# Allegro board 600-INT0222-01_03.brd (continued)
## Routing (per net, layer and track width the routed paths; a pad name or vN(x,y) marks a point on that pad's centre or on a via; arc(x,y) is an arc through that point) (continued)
P10_6_VBEMF_V/IV(2)_L: length 9
  BOTTOM w0.203: J13.3 51.28,3.95 51.58,4.25 51.58,8.67 J15.1
P10_6_VBEMF_V/IV(2)_R: length 13.5
  TOP w0.203: J15.3 56.94,8.95 52.82,8.95 51.6,7.73 51.6,4.43 51.28,4.11 J13.4
P10_7_VBEMF_V/IV(3)/PFC_I_PHASE_IN_B: length 95.9
  TOP w0.203: v1(18.94,49.34) 19.28,49 19.28,45 18.25,43.97 16.66,43.97 16.13,43.43 16.13,43.05 15.23,42.15 13.69,42.15 12.79,43.05 11.88,43.05 10.98,42.15 8.73,42.15 J1.B29 ; J19.2 56.99,65.82 56.01,66.8 51.99,66.8 51.52,67.27 44.78,67.27 43.71,68.34 42.99,68.34 J5.16 41.67,68.2 42.14,67.73 43.25,67.73 44.48,66.5 49.96,66.5 51.09,65.37 51.09,63.59 48.51,61.02 48.51,56.65 48.07,56.21 47.42,56.21 v1(47.01,55.79) J12.C7
  L03_SIG1 w0.203: v1(18.94,49.34) 19.28,49.68 19.28,50.85 21.19,52.76 46.03,52.76 48.01,54.74 48.01,55.95 47.73,56.23 47.44,56.23 v1(47.01,55.79)
P10_7_VBEMF_V/IV(3)/PFC_I_PHASE_IN_B_L: length 21.5
  BOTTOM w0.203: J19.1 55.72,65.8 63.54,65.8 64.18,66.43 68.29,66.43 69.87,68.01 69.87,70.59 70.14,70.86 J2.3
P10_7_VBEMF_V/IV(3)/PFC_I_PHASE_IN_B_N: length 79.8
  TOP w0.203: J5.17 42.85,70.83 41.18,70.83 40.49,70.14 40.49,68.81 41.97,67.33 43.08,67.33 44.31,66.1 49.79,66.1 50.68,65.2 50.68,63.76 48.11,61.19 48.11,56.82 47.9,56.62 47.46,56.62 v1(47.01,57.07) J12.B7 ; v1(20.03,49.34) 19.68,49 19.68,44.83 18.41,43.56 16.83,43.56 16.59,43.32 R20.1 16.07,42.42 15.4,41.74 13.52,41.74 13.12,42.15 12.54,42.15 J1.A29
  L03_SIG1 w0.203: v1(20.03,49.34) 19.68,49.68 19.68,50.68 21.36,52.36 46.2,52.36 48.41,54.57 48.41,56.12 47.9,56.64 47.44,56.64 v1(47.01,57.07)
P10_7_VBEMF_V/IV(3)/PFC_I_PHASE_IN_B_R: length 23.8
  TOP w0.203: v1(73.95,65.52) 73.95,65.75 70.14,69.56 J2.4
  L03_SIG1 w0.203: J19.3 60.91,65.91 73.56,65.91 v1(73.95,65.52)
P11_0_VBEMF_U/IU(1): length 121.8
  TOP w0.203: v1(90.21,33.39) 87.88,35.71 87.88,40.51 89.76,42.39 93.86,42.39 96.59,45.12 98.39,45.12 J4.A5 ; v1(50.9,28.02) 50.56,28.36 49.75,28.36 49.55,28.15 J10.C8
  L03_SIG1 w0.203: v1(90.21,33.39) 87.43,30.61 52.83,30.61 51.69,29.46 51.69,28.24 51.46,28.02 v1(50.9,28.02) 50.56,28.36 50.27,28.36 49.94,28.02 49.94,26.44 47.6,24.1 22.77,24.1 21.01,22.34 21.01,17.2 19.15,15.34 17.75,15.34 17.14,14.73 17.14,12.36 16.35,11.56 13.74,11.56 12.57,12.74 J1.B6
P11_0_VBEMF_U/IU(1)_N: length 55.7
  TOP w0.203: R23.1 14.28,12.7 J1.A6 ; J10.B8 49.55,28.97 49.75,28.76 50.56,28.76 v1(50.9,29.11)
  L03_SIG1 w0.203: J1.A6 14.22,12.72 14.97,11.97 16.18,11.97 16.74,12.53 16.74,14.9 17.59,15.75 18.98,15.75 20.6,17.36 20.6,22.5 22.61,24.51 47.43,24.51 49.53,26.61 49.53,28.19 50.11,28.76 50.56,28.76 v1(50.9,29.11)
P11_1_VBEMF_V/IV(1): length 119.8
  TOP w0.203: v1(47.01,28.02) J10.C7 ; J4.A6 98.39,42.58 96.59,42.58 95.41,41.4 89.79,41.4 88.62,40.23 88.62,36.6 v1(90.21,35.01)
  L03_SIG1 w0.203: v1(90.21,35.01) 86.69,31.5 47.37,31.5 46.41,30.53 46.41,28.62 v1(47.01,28.02) 47.38,28.39 47.67,28.39 48.15,27.91 48.15,26.94 46.74,25.53 21.84,25.53 18.2,21.88 18.2,18.65 15.47,15.92 15.47,14.65 15.03,14.21 13.8,14.21 12.94,15.07 11.73,15.07 10.67,14.01 J1.B7
P11_1_VBEMF_V/IV(1)_N: length 54
  TOP w0.203: v1(47.01,29.18) J10.B7 ; R16.1 12.42,14.1 J1.A7
  L03_SIG1 w0.203: J1.A7 13.43,14.01 13.63,13.8 15.2,13.8 15.88,14.48 15.88,15.75 18.61,18.48 18.61,21.71 22.01,25.12 46.9,25.12 48.56,26.77 48.56,28.08 47.84,28.8 47.38,28.8 v1(47.01,29.18)
P11_2_VBEMF_W/IW(1): length 112.3
  TOP w0.203: v1(90.21,36.92) 89.28,37.85 89.28,39.62 90.18,40.52 95.37,40.52 95.85,40.04 98.39,40.04 J4.A7 ; v1(44.47,28.02) J10.C6
  L03_SIG1 w0.203: v1(90.21,36.92) 90.13,36.92 85.34,32.13 45.47,32.13 43.87,30.53 43.87,28.62 v1(44.47,28.02) 44.84,28.39 45.13,28.39 45.39,28.14 45.39,27.42 44.41,26.44 21.11,26.44 17.27,22.61 17.27,19.34 14.68,16.75 14.05,16.75 12.78,15.48 10.63,15.48 J1.B8
P11_2_VBEMF_W/IW(1)_N: length 46.5
  TOP w0.203: v1(44.47,29.18) J10.B6 ; J1.A8 15.6,16.64 R17.1
  L03_SIG1 w0.203: J1.A8 14.24,15.73 17.68,19.17 17.68,22.44 21.28,26.04 44.58,26.04 45.8,27.25 45.8,28.3 45.3,28.8 44.84,28.8 v1(44.47,29.18)
P12_0_PFC_V_PHASE_IN_B: length 193.5
  TOP w0.203: v1(86.12,11.87) 87.11,12.87 87.11,49.19 v1(86.11,50.2) 86.58,50.67 96.12,50.67 96.59,50.2 98.39,50.2 J4.A4 ; J12.C17 v1(72.41,55.87) 71.17,57.1 71.17,61.45 72.39,62.67 72.39,65.58 70.71,67.27 63.79,67.27 62.86,68.21 62.86,72.4 61.74,73.52 59.47,73.52 J8.7
  L03_SIG1 w0.203: J7.7 64.39,3.98 64.39,6.55 65.93,8.09 73.75,8.09 78.36,12.7 85.29,12.7 v1(86.12,11.87) ; v1(86.11,50.2) 82.6,53.71 74.57,53.71 v1(72.41,55.87) 72.41,55.98 71.59,56.8 71.59,57.08 68.56,60.12 21.73,60.12 18.31,63.54 J1.A46
P12_5_PFC_OVERCURRENT_PROT: length 73.6
  TOP w0.305: J12.C19 v1(77.49,55.87)
  L03_SIG1 w0.203: J1.A47 12.33,65.76 13.91,67.34 20.58,67.34 25.35,62.56 70.8,62.56 v1(77.49,55.87)
P12_6_PFC_NTC: length 76.4
  TOP w0.203: J12.B19 v1(77.49,57.13)
  L03_SIG1 w0.203: J1.B48 10.43,67.03 13.14,69.74 15.86,69.74 16.38,69.22 20.14,69.22 26.19,63.17 71.45,63.17 v1(77.49,57.13)
P13_0_U3_H/PFC_PWM_A_1: length 113.7
  TOP w0.152: J12.C1 v1(31.77,55.79)
  LO4_SIG2 w0.152: J5.1 22.55,70.85 22.55,66.08 30.73,57.89 30.73,56.82 v1(31.77,55.79) 31.77,49.9 v1(29.73,47.87)
  BOTTOM w0.152: v1(29.73,47.87) 27.84,45.97 16.8,45.97 15.52,47.25 13.73,47.25 12.69,48.3 J1.B34 ; J2.17 75.74,70.98 76.33,70.39 76.52,70.39 77.38,69.53 77.38,63.92 74.62,61.15 33.84,61.15 30.86,58.17 30.86,56.7 v1(31.77,55.79)
P13_1_U3_L/PFC_PWM_A_2: length 108.1
  TOP w0.152: J12.B1 v1(31.77,57.07)
  LO4_SIG2 w0.152: J5.3 25.12,70.89 25.12,64.82 31.77,58.18 v1(31.77,57.07) 32.64,56.2 32.64,49.23 30.4,46.99 28.96,46.99 28.11,47.84 v1(28.11,47.87)
  BOTTOM w0.152: v1(28.11,47.87) 27.23,46.99 19.3,46.99 18,48.3 J1.A34 ; v1(31.77,57.07) 32.1,57.4 32.21,57.4 35.45,60.64 75.02,60.64 78.27,63.89 78.27,69.29 76.54,71.02 J2.19
P13_2_V3_H/PFC_PWM_B_1: length 110.6
  TOP w0.152: J12.B2 v1(34.31,57.07)
  LO4_SIG2 w0.152: v1(34.31,57.07) 27.66,63.72 27.66,70.89 J5.5
  BOTTOM w0.152: J2.31 81.34,65.08 75.83,59.57 36.81,59.57 v1(34.31,57.07) 34.84,56.54 34.84,54.78 32.38,52.32 13.59,52.32 12.77,53.15 11.9,53.15 10.85,52.1 10.11,52.1 8.53,50.51 J1.B35
P13_3_V3_L/PFC_PWM_B_2: length 120.4
  TOP w0.152: J12.C2 v1(34.31,55.79)
  LO4_SIG2 w0.152: J5.7 30.25,70.94 30.25,68.33 30.81,67.77 30.81,62.2 35.18,57.84 35.18,56.67 v1(34.31,55.79)
  BOTTOM w0.152: J2.29 80.54,65.3 75.38,60.13 35.75,60.13 33.66,58.04 33.66,56.44 v1(34.31,55.79) 34.31,55.69 31.32,52.7 16.64,52.7 14.73,54.61 14,54.61 13,53.61 11.9,53.61 11.09,54.42 10,54.42 8.79,53.21 8.16,53.21 7.48,52.54 7.48,49.14 8.09,48.53 9.03,48.53 10.07,49.57 J1.A35
P13_4_W3_H/PFC_PWM_C_1: length 107.3
  TOP w0.152: v1(35.9,56.06) 35.9,55.71 36.85,54.77 J12.C3
  LO4_SIG2 w0.152: J5.9 32.91,71.06 32.91,69.19 34.8,67.3 34.8,60.5 35.9,59.4 v1(35.9,56.06)
  BOTTOM w0.152: J1.B36 12.77,50.84 13.87,51.94 33.1,51.94 35.9,54.75 v1(35.9,56.06) 35.9,57.37 37.65,59.12 76.39,59.12 82.14,64.86 J2.33
P13_5_W3_L/PFC_PWM_C_2: length 102.5
  TOP w0.152: J12.B3 v1(36.85,57.07)
  LO4_SIG2 w0.152: v1(36.85,57.07) 37.19,57.41 37.19,64.75 36.59,65.34 36.59,68.05 37.73,69.19 37.73,71.06 J5.11
  BOTTOM w0.152: J1.A36 14.46,51.05 33.4,51.05 36.85,54.5 v1(36.85,57.07) 38.38,58.61 77.03,58.61 82.94,64.52 J2.35
P14_0_V4_H: length 128.4
  TOP w0.152: J9.C13 v1(62.25,45.63)
  LO4_SIG2 w0.152: J1.B39 10.76,54.65 11.8,55.69 12.92,55.69 13.73,54.88 17.13,54.88 20.95,51.05 20.95,47.57 25.74,42.79 59.4,42.79 v1(62.25,45.63)
  BOTTOM w0.152: J6.5 93.54,3.92 93.54,10.55 84.28,19.81 82.69,19.81 79.07,23.44 79.07,39.75 76.28,42.55 65.33,42.55 v1(62.25,45.63)
P16_3_ADC_BOARDIDENT/EXTRA_ADC4: length 59.4
  TOP w0.203: J12.C15 67.33,55.58 65.95,56.96 v1(64.79,56.96) J12.B14
  L03_SIG1 w0.203: J1.A44 15.21,61 17.33,58.88 19.42,58.88 19.8,58.49 63.25,58.49 v1(64.79,56.96)
P17_0_PFC_V_PHASE_IN_C: length 71.5
  TOP w0.203: J12.C18 v1(74.95,55.87)
  L03_SIG1 w0.203: J1.B46 12.65,63.54 13.81,64.69 15.16,64.69 16.04,65.57 19.42,65.57 23.65,61.34 69.48,61.34 v1(74.95,55.87)
P17_3_VBEMF_W/IW(4): length 122.3
  TOP w0.203: v1(24.87,49.59) 24.87,50.61 15.75,59.73 J1.A43 ; v1(84,41.9) 82.8,40.7 82.8,9.6 80.3,7.1 78.93,7.1 J6.18 ; J9.C7 v1(47.01,45.71)
  L03_SIG1 w0.203: v1(84,41.9) 81.57,41.9 80.44,43.03 49.69,43.03 v1(47.01,45.71) 42.77,49.95 25.22,49.95 v1(24.87,49.59)
P17_4_VBEMF_W/IW(2): length 119.9
  TOP w0.203: v1(44.47,17.77) J11.C6 44.47,11.92 J16.2 ; v1(24.55,20.84) 16.14,29.25 13.92,29.25 12.73,30.44 12,30.44 10.81,29.25 J1.B19
  L03_SIG1 w0.203: v1(24.55,20.84) 25.35,21.64 43.19,21.64 45.28,19.55 45.28,18.58 v1(44.47,17.77) 46.12,16.12 51.48,16.12 52.81,17.45 52.81,19.48 56.06,22.73 81.04,22.73 81.05,22.74 83.07,22.74 93.89,33.57 93.89,38.21 96.99,41.31 J4.B7
P17_4_VBEMF_W/IW(2)_L: length 13.4
  L03_SIG1 w0.203: v1(48.4,7.4) 47.04,8.76 45.09,8.76 J16.1
  BOTTOM w0.203: J13.5 50.48,4.02 50.97,4.51 50.97,5.96 50.13,6.79 49.01,6.79 v1(48.4,7.4)
P17_4_VBEMF_W/IW(2)_R: length 9.5
  TOP w0.203: J13.6 50.48,4.19 50.97,4.69 50.97,6.42 v1(49.78,7.61)
  L03_SIG1 w0.203: J16.3 49.78,9.14 v1(49.78,7.61)
P17_5_VBEMF_W/IW(3)/PFC_I_PHASE_IN_C: length 105.4
  TOP w0.203: 62,62.89 60.71,61.59 51.44,61.59 51.05,61.21 51.05,56.68 50.61,56.24 49.99,56.24 v1(49.55,55.79) J12.C8 ; 62,62.89 62,65.12 59.27,67.84 52.49,67.84 52.11,68.22 49.36,68.22 48.49,69.1 48.49,72.31 47.31,73.49 46.19,73.49 45.47,72.76 45.47,70.91 J5.18 ; 62,62.89 62.3,62.59 65.64,62.59 J20.2
  L03_SIG1 w0.203: J1.B30 12.73,43.22 14.12,44.6 14.84,44.6 14.89,44.55 18.42,44.55 20.92,47.05 20.92,50.58 22.02,51.67 49,51.67 50.93,53.59 50.93,55.63 50.32,56.23 49.98,56.23 v1(49.55,55.79)
P17_5_VBEMF_W/IW(3)/PFC_I_PHASE_IN_C_L: length 11.8
  BOTTOM w0.203: J2.5 70.94,70.8 70.48,70.34 70.48,67.76 68.54,65.82 66.33,65.82 J20.1
P17_5_VBEMF_W/IW(3)/PFC_I_PHASE_IN_C_N: length 91.9
  TOP w0.203: J12.B8 v1(49.55,57.07) 49.98,56.64 50.44,56.64 50.65,56.85 50.65,61.38 51.27,62 60.54,62 61.59,63.06 61.59,64.95 59.11,67.44 52.32,67.44 51.94,67.82 49.19,67.82 48.08,68.93 48.08,70.87 J5.19 ; R21.1 16.23,45.21 J1.A30
  L03_SIG1 w0.203: v1(49.55,57.07) 49.98,56.64 50.49,56.64 51.33,55.79 51.33,53.43 49.17,51.27 22.19,51.27 21.33,50.41 21.33,46.88 18.59,44.15 15.06,44.15 14.24,43.32 J1.A30
P17_5_VBEMF_W/IW(3)/PFC_I_PHASE_IN_C_R: length 17.7
  TOP w0.203: v1(74.73,67.51) 74.67,67.51 73.35,68.83 71.91,68.83 70.94,69.8 J2.6
  L03_SIG1 w0.203: v1(74.73,67.51) 74.73,67.41 75.61,66.53 75.61,64.18 74.55,63.12 72.92,63.12 71.51,64.53 J20.3
P17_6_IAVG_IDCLINK(3): length 89
  TOP w0.203: J5.14 39.13,68.12 42.04,65.21 42.04,63.78 42.89,62.93 45.1,62.93 J21.2 46.6,61.84 45.85,61.09 45.85,56.58 45.39,56.12 44.79,56.12 v1(44.47,55.79) J12.C6
  L03_SIG1 w0.203: J8.6 54.22,68.26 40.53,68.26 J5.14 ; J1.B31 8.52,45.46 10.09,47.03 10.76,47.03 11.87,48.13 12.8,48.13 13.71,47.23 15.86,47.23 17.02,48.39 17.02,51.25 19.64,53.87 44.73,53.87 45.59,54.74 45.59,55.83 45.18,56.24 44.91,56.24 v1(44.47,55.79)
P17_6_IAVG_IDCLINK(3)_L: length 39.6
  BOTTOM w0.203: J21.1 45.87,62.61 71.48,62.61 73.02,64.15 73.02,66.42 73.8,67.21 73.8,68.82 72.66,69.97 72.66,70.85 72.54,70.97 J2.9
P17_6_IAVG_IDCLINK(3)_N: length 50.8
  TOP w0.203: R24.1 15.31,45.32 15.31,45.32 14.68,44.69 14.68,44.69 14.47,44.49 J1.A31 ; J12.B6 v1(44.47,57.07)
  L03_SIG1 w0.203: J1.A31 12.33,45.48 13.68,46.82 16.03,46.82 17.42,48.22 17.42,51.08 19.81,53.47 44.9,53.47 46,54.57 46,55.99 45.35,56.64 44.9,56.64 v1(44.47,57.07)
P17_7_IDCLINK(4): length 156.8
  TOP w0.203: v1(84,43.8) 82.08,41.88 82.08,10.07 80.38,8.37 68.77,8.37 J7.6 ; v1(22.14,50.07) 22.14,50.46 17.61,54.99 14.99,54.99 14.6,54.61 13.97,54.61 12.62,55.96 11.99,55.96 10.71,57.24 10.05,57.24 8.52,58.76 J1.B43 ; J9.B7 v1(47.01,46.97)
  L03_SIG1 w0.203: v1(84,43.8) 81.19,43.8 80.9,44.09 49.88,44.09 v1(47.01,46.97) 43.42,50.56 24.97,50.56 24.96,50.55 22.62,50.55 v1(22.14,50.07) ; J6.14 80.08,7.48 67.88,7.48 J7.6
P18_0_PFC_RELAY1: length 66.8
  TOP w0.152: J9.C11 v1(57.17,45.71)
  LO4_SIG2 w0.152: J1.A49 12.56,67.12 18.23,67.12 23.02,62.32 23.02,54.41 26.16,51.27 26.16,49.05 25.34,48.23 25.34,46.54 26.92,44.96 31.34,44.96 31.39,45.01 31.41,45.01 34.21,47.81 55.06,47.81 v1(57.17,45.71)
P18_1_PFC_RELAY2: length 69.8
  TOP w0.152: J9.B12 v1(59.71,46.97)
  LO4_SIG2 w0.152: J1.B49 10.78,67.35 12.08,66.05 12.69,66.05 13.95,64.79 15.25,64.79 16,64.03 16,59.64 25.71,49.94 25.71,49.24 24.88,48.42 24.88,46.24 26.76,44.36 57.1,44.36 59.71,46.97 v1(59.71,46.97)
P18_2_ENPOW3: length 107.6
  TOP w0.152: J9.C16 v1(69.87,45.71)
  LO4_SIG2 w0.152: J1.B33 10.76,47.03 12,48.26 12.73,48.26 14,46.99 14.6,46.99 17.6,43.99 20.6,43.99 24.73,39.86 64.02,39.86 v1(69.87,45.71) ; v1(82.59,62.09) 82.59,52.06 v1(81.45,50.91)
  BOTTOM w0.152: v1(82.59,62.09) 84.54,64.04 J2.39 ; v1(69.87,45.71) 70.3,45.28 73.34,45.28 74.04,45.97 74.04,47.14 77.81,50.91 v1(81.45,50.91)
P18_3_ENPOW4: length 72.1
  TOP w0.152: J9.B16 v1(69.87,46.97)
  LO4_SIG2 w0.152: J1.B37 10.75,52.11 11.95,50.91 12.59,50.91 13.94,49.56 14.62,49.56 15.75,48.43 15.75,46.61 17.85,44.5 20.74,44.5 24.87,40.37 63.26,40.37 v1(69.87,46.97)
P18_4_W4_H: length 124.4
  TOP w0.152: J9.C12 v1(59.71,45.71)
  LO4_SIG2 w0.152: J1.B40 10.66,56.15 12.84,56.15 13.65,56.96 17.34,56.96 22.99,51.31 22.99,49.53 22.24,48.78 22.24,47.57 26.01,43.8 57.8,43.8 v1(59.71,45.71)
  BOTTOM w0.152: v1(59.71,45.71) 63.63,41.78 76.07,41.78 78.31,39.55 78.31,22.66 82.17,18.8 82.17,18.16 89.07,11.26 89.07,6.15 88.72,5.79 88.72,4.18 J6.9
P18_5_W4_L: length 129.3
  TOP w0.152: J9.B13 v1(62.25,47.05)
  LO4_SIG2 w0.152: J1.A40 17.11,55.92 21.34,51.69 21.34,47.83 25.82,43.34 58.54,43.34 v1(62.25,47.05)
  BOTTOM w0.152: v1(62.25,47.05) 61.64,47.65 59.48,47.65 59.07,47.24 59.07,45.16 62.83,41.4 75.18,41.4 76.83,39.75 76.83,39.28 77,39.11 77,38.58 76.83,38.42 76.83,22.73 79.72,19.85 80.29,19.85 81.03,19.11 81.03,17.96 85.82,13.17 86.66,13.17 88.39,11.44 88.39,7.62 87.38,6.61 86.78,6.61 86.02,5.86 86.02,4.03 J6.11
P18_6_PWM_SYNCHRO_RECT_HIGH: length 198.3
  TOP w0.152: J9.B17 v1(72.41,46.97)
  LO4_SIG2 w0.152: v1(40.93,64.12) 40.93,62.82 44.02,59.73 48.83,59.73 57.77,50.79 68.59,50.79 v1(72.41,46.97)
  BOTTOM w0.152: J1.A50 16.2,66.66 38.62,66.66 40.93,64.35 v1(40.93,64.12) 41.53,64.72 41.53,66.42 40.46,67.49 40.46,70.31 41.15,70.99 49.33,70.99 J8.1 ; J7.1 69.37,1.35 64.92,1.35 64.53,1.74 64.53,4.62 64.33,4.82 64.33,6.84 66.33,8.85 69.81,8.85 70.63,9.67 70.63,13.17 66.49,17.31 66.49,19.49 68.71,21.71 68.71,30.23 57.81,41.13 57.81,47.39 58.93,48.51 70.86,48.51 v1(72.41,46.97) 78.15,52.72 98.36,52.72 J4.A2
P18_7_PWM_SYNCHRO_RECT_LOW: length 68.9
  TOP w0.152: J9.B11 v1(57.17,46.97)
  LO4_SIG2 w0.152: J1.B50 12.61,68.62 13.65,67.57 18.42,67.57 23.53,62.46 23.53,54.55 26.62,51.46 26.62,48.86 25.8,48.04 25.8,46.85 27.18,45.47 31.22,45.47 34.34,48.59 55.55,48.59 v1(57.17,46.97)
P19_0_PFC_V_DC_OUT_1: length 70
  TOP w0.203: v1(18.49,64.76) 13.96,64.76 12.84,65.88 11.82,65.88 10.75,64.81 J1.B47
  TOP w0.305: J12.B17 v1(72.41,57.13)
  L03_SIG1 w0.203: v1(72.41,57.13) 68.81,60.73 23.4,60.73 23.29,60.83 22.41,60.83 v1(18.49,64.76)
P19_1_PFC_V_DC_OUT_2: length 66.8
  TOP w0.203: J12.B18 v1(74.95,57.13)
  L03_SIG1 w0.203: J1.A48 14.56,66.4 20.09,66.4 24.54,61.95 70.13,61.95 v1(74.95,57.13)
P20_0_EXTRA _ADC1/DC_LINK2: length 98.8
  TOP w0.203: J12.B4 39.39,61.18 38.21,62.36 32.13,62.36 v1(29.97,64.52) 23.88,58.42 21.59,58.42 20.38,57.21 v1(20.38,56.45) ; J1.A32 14.24,46.37 17.1,49.23 v1(17.1,53.61)
  L03_SIG1 w0.203: v1(17.1,53.61) 18.86,55.37 19.3,55.37 v1(20.38,56.45) ; v1(72.99,67.95) 72.18,67.13 63.42,67.13 62.48,68.07 62.48,72.9 61.82,73.57 43.04,73.57 J5.15 40.36,70.89 38.62,70.89 37.91,70.18 37.91,69.11 36.49,67.69 33.15,67.69 v1(29.97,64.52)
  BOTTOM w0.203: v1(72.99,67.95) 72.23,67.95 71.24,68.94 71.24,70.24 71.74,70.74 J2.7
P20_1_EXTRA_ADC2/DC_LINK3: length 149.9
  TOP w0.203: v1(27.09,17.59) 27.09,24.25 21.08,30.26 v1(21.08,42.16) ; J9.C4 v1(39.39,45.71)
  L03_SIG1 w0.203: J1.B32 10.43,44.79 9.35,43.71 9.35,42.68 10.12,41.92 10.82,41.92 11.91,40.82 12.77,40.82 13.71,41.76 20.68,41.76 v1(21.08,42.16) 37.34,42.16 39.39,44.21 v1(39.39,45.71) ; v1(27.09,17.59) 27.09,11.9 33.11,5.88 50.33,5.88 51.22,6.77 v1(51.22,9.89) 51.45,9.89 52.7,8.64 58.67,8.64 59.33,7.98 59.33,2.23 60.1,1.46 60.13,1.46 60.22,1.37 78.29,1.37 J6.15
  BOTTOM w0.203: v1(51.22,9.89) 50.6,9.27 50.3,9.27 49.28,8.26 47.55,8.26 47.28,7.99 47.28,6.97 47.67,6.59 48.35,6.59 49.32,5.63 49.32,4.56 49.68,4.2 J13.7
P20_2_EXTRA_ADC3: length 65.6
  TOP w0.203: J12.C16 v1(69.87,51.5)
  L03_SIG1 w0.203: J1.B44 12.62,61 13.81,59.81 15,59.81 16.69,58.12 19.32,58.12 19.55,57.88 59.02,57.88 65.41,51.5 v1(69.87,51.5)
P23_3_CTRAP4: length 122.4
  TOP w0.152: v1(67.33,45.71) J9.C15 67.33,41.11 67.03,40.82 v1(67.03,39.19)
  LO4_SIG2 w0.152: J1.A37 12.56,51.88 14.95,51.88 16.61,50.22 16.61,49.27 24.98,40.91 62.52,40.91 v1(67.33,45.71)
  BOTTOM w0.152: J6.13 83.64,4.18 83.64,5.79 84.95,7.11 86.87,7.11 87.66,7.91 87.66,11.52 86.47,12.71 85.43,12.71 76.33,21.82 76.33,37.47 74.38,39.41 67.86,39.41 67.64,39.19 v1(67.03,39.19)
P_14_1_V4_L: length 131.2
  TOP w0.152: J9.B14 v1(64.79,47.04)
  LO4_SIG2 w0.152: v1(64.79,47.04) 60.04,42.29 25.58,42.29 20.57,47.3 20.57,50.55 19.3,51.82 17.65,51.82 15.05,54.42 12.56,54.42 J1.A39
  BOTTOM w0.152: J6.7 89.86,3.71 91.26,5.11 91.26,12.4 84.86,18.8 83.28,18.8 78.74,23.34 78.74,39.65 76.23,42.16 64.6,42.16 61.37,45.4 61.37,45.92 61.8,46.35 62.97,46.35 63.65,47.04 v1(64.79,47.04)
PWR_IN_5V: length 25.2
  TOP w0.254: Q6.4 71.86,36.75 71.96,36.65 R1.2 ; Q8.4 57.26,36.75 57.36,36.65 R8.2 ; Q10.4 41.38,36.75 41.48,36.65 R12.2
  TOP w0.762: v1(44.05,35.61) Q9.S 42.53,36.45 R12.2 ; R8.2 58.41,36.45 Q7.S v1(59.93,35.61) ; v1(74.53,35.61) Q5.S 73.01,36.45 R1.2 ; J10.B17 v1(72.41,29.19)
  L03_SIG1 w0.381: 7.81,10.76 J1.B5 ; J1.B5 7.81,12.18 ; J1.B5 9.23,10.76 ; J1.B5 9.23,12.18
  BOTTOM w0.381: 9.72,17.11 J1.B10 ; J1.B10 11.14,17.11 ; J1.B10 9.72,18.53 ; 7.81,10.76 J1.B5 ; J1.B5 7.81,12.18 ; J1.B5 9.23,12.18
PWR_IN_24V*: length 23.6
  TOP w0.381: 25.23,35.7 D2.K ; D2.K 26.16,34.42 ; D2.K 27.09,35.7 ; D2.K 26.16,36.98 ; 30.9,31.29 J10.B1 ; J10.B1 32.63,31.29 ; J10.B1 31.77,29.47 ; J10.B1 31.77,33.11 ; 30.9,43.61 J9.C1 ; J9.C1 32.63,43.61 ; J9.C1 31.77,45.43 ; J9.C1 31.77,41.79 ; 26.16,37.97 D1.K ; D1.K 26.16,40.54 ; D1.K 27.09,39.25 ; D1.K 25.23,39.25
  BOTTOM w0.381: J1.B41 9.23,57.9 ; J1.B41 7.81,56.48 ; J1.B41 9.23,56.48 ; J1.B41 7.81,57.9
  vias: v1(22.8,38.47) v1(24.42,38.47)
PWR_OUT_SYS: length 10.8
  TOP w0.381: J10.B19 78.35,31.29 ; J10.B19 76.62,31.29 ; J10.B19 77.49,33.11 ; J10.B19 77.49,29.47 ; 77.49,41.79 J9.C19 ; J9.C19 77.49,45.43 ; J9.C19 76.62,43.61 ; J9.C19 78.35,43.61
SH1-1: length 201.4
  TOP w0.305: v1(73.84,62.08) 75.63,63.87 75.63,67.83 73.97,69.49 73.14,69.49 72.61,70.02 72.61,72.5 J2.10 ; J13.10 48.88,5.56 45.81,8.62 40.12,8.62 J17.3
  L03_SIG1 w0.305: v1(73.84,62.08) 76.24,59.68 99.58,59.68 101.89,57.36 101.89,17.26 99.55,14.91 90.94,14.91 87.94,17.91 83.95,17.91 81.91,15.88 74.55,15.88 73.41,14.73 62.36,14.73 60.45,12.83 40.06,12.83 38.09,10.86 J17.3
  LO4_SIG2 w0.305: v1(73.84,62.08) 72.75,60.99 65.87,60.99 59.49,54.61 56.85,54.61 55.85,55.6 55.85,57.71 J21.3
N2988165: length 11.4
  TOP w0.305: Q5.G 75.21,38.35 75.48,38.09 75.48,35.17 75.12,34.81 71.26,34.81 R7.1 70.65,35.93 69.83,36.75 Q6.3
N2988205: length 11.6
  TOP w0.305: Q7.G 60.74,38.35 61,38.09 61,35.29 60.52,34.81 56.65,34.81 R11.1 56.04,35.92 55.21,36.75 Q8.3
N2988245: length 11.5
  TOP w0.305: Q10.3 39.35,36.75 40.17,35.93 R15.1 40.8,34.78 44.75,34.78 45,35.04 45,38.05 44.69,38.35 Q9.G
N2988267: length 3.4
  TOP w0.305: R6.2 67.83,37.4 Q6.2 Q6.5
N2988279: length 3
  TOP w0.305: R10.2 53.6,37.4 Q8.2 Q8.5
N2988291: length 3.4
  TOP w0.305: R14.2 37.35,37.4 Q10.2 Q10.5
N2988319: length 1.6
  TOP w0.305: R5.1 70.65,39.36 71.14,38.87 Q6.6
N2988327: length 1.6
  TOP w0.305: R9.1 56.04,39.36 56.54,38.87 Q8.6
N2988335: length 1.6
  TOP w0.305: Q10.6 40.66,38.87 40.17,39.36 R13.1

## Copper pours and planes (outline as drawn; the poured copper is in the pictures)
3.3V_PWR_OUT_SYS on BOTTOM: 31.65,47.32 32.44,47.32 33.06,46.7 33.06,43.42 30.1,40.46 30.1,33.91 28.43,32.24 21.07,32.24 17.4,28.57 14.73,28.57 14.73,28.45 17.27,28.45 16.89,28.07 7.39,28.07 6.77,28.69 6.77,32.81 7.37,33.4 9.78,33.4 9.78,33.53 7.49,33.53 7.82,33.86 15.88,33.86 17.2,35.18 24.51,35.18 25.91,36.58 25.91,41.58 ; 1 cut-out
AGND on TOP: outline of 361 points within 0.51,0.51 104.49,74.49 ; 64 cut-outs
AGND on BOTTOM: 69.38,74.28 74.21,74.28 74.34,74.15 74.34,69.58 74.97,68.95 74.97,63.99 74.08,63.11 73.7,63.11 72.94,62.34 43.3,62.34 42.42,63.22 42.42,66.17 43.81,67.56 56.06,67.56 56.77,68.28 56.77,73.79 57.26,74.28 63.55,74.28 63.62,74.15 63.64,74 63.64,67.58 62.74,66.67 62.99,66.67 63.88,67.56 63.88,68.59 64.43,68.08 65.15,67.89 67.85,67.89 68.56,68.19 68.86,68.9 68.86,73.76 ; 5 cut-outs
AGND on L02_AGND: 68.86,74.49 93.09,74.49 93.09,68.9 93.39,68.19 94.1,67.89 96.8,67.89 97.87,68.33 98.31,69.4 98.31,73.79 102.87,73.79 103.89,72.77 104.47,72.77 104.49,72.64 104.49,72.5 104.49,2.5 103.91,1.09 102.5,0.51 60.07,0.51 57.76,2.82 57.76,5.6 57.32,6.67 56.25,7.11 53.55,7.11 52.84,6.81 52.54,6.1 52.54,0.51 28.31,0.51 28.31,6.1 28.01,6.81 27.3,7.11 24.6,7.11 23.53,6.67 23.09,5.6 23.09,1 22.95,0.65 22.6,0.51 2.5,0.51 1.09,1.09 0.51,2.5 0.51,72.5 1.09,73.91 2.5,74.49 63.15,74.49 63.5,74.35 63.64,74 63.64,69.4 64.08,68.33 65.15,67.89 67.85,67.89 68.56,68.19 68.86,68.9 ; 14 cut-outs
AGND on L03_SIG1: 98.31,74 98.45,74.35 98.8,74.49 102.5,74.49 103.91,73.91 104.49,72.5 104.49,2.5 103.91,1.09 102.5,0.51 58.25,0.51 57.9,0.65 57.76,1 57.76,5.6 57.32,6.67 56.25,7.11 53.55,7.11 52.84,6.81 52.54,6.1 52.54,0.51 28.31,0.51 28.31,6.1 28.01,6.81 27.3,7.11 24.6,7.11 23.53,6.67 23.09,5.6 23.09,1 22.95,0.65 22.6,0.51 2.5,0.51 1.09,1.09 0.51,2.5 0.51,72.5 1.09,73.91 2.5,74.49 63.15,74.49 63.5,74.35 63.64,74 63.64,69.4 64.08,68.33 65.15,67.89 67.85,67.89 68.56,68.19 68.86,68.9 68.86,74.49 93.09,74.49 93.09,68.9 93.39,68.19 94.1,67.89 96.8,67.89 97.87,68.33 98.31,69.4 ; 76 cut-outs
AGND on L05_DGND: 57.26,74.28 63.55,74.28 63.62,74.15 63.64,74 63.64,69.4 64.08,68.33 65.15,67.89 67.85,67.89 68.56,68.19 68.86,68.9 68.86,73.76 69.38,74.28 74.21,74.28 74.34,74.15 74.34,69.58 74.97,68.95 74.97,63.67 74.3,62.99 73.59,62.99 72.94,62.34 43.3,62.34 42.42,63.22 42.42,66.17 43.81,67.56 56.06,67.56 56.77,68.28 56.77,73.79
GND on TOP: 65.66,41.15 67.18,41.15 67.73,40.6 67.73,37.2 68.49,36.44 69.89,36.44 70.4,35.93 70.4,33.82 70.23,33.66 36.83,33.66 36.2,34.29 36.2,35.21 34.71,36.69 34.71,40.81 35.05,41.15 36.83,41.15 37.25,40.73 37.25,37.2 38.01,36.44 39.41,36.44 39.92,35.93 39.92,34.91 40.54,34.29 44.96,34.29 46.23,35.56 48.9,35.56 49.4,36.07 49.4,40.64 49.91,41.15 52.58,41.15 53.09,40.64 53.09,37.24 53.89,36.44 55.29,36.44 55.79,35.93 55.79,35.05 56.43,34.42 60.83,34.42 62.1,35.69 64.52,35.69 65.15,36.32 65.15,38.73 65.41,38.99 66.29,38.99 66.55,38.74 66.55,37.73 67.31,37.73 67.31,37.72 67.56,37.97 67.56,38.73 67.06,39.24 65.15,39.24 65.15,40.64
GND on BOTTOM: outline of 90 points within 0.51,0.51 104.49,74.49 ; 76 cut-outs
GND on LO4_SIG2: 98.31,74 98.45,74.35 98.8,74.49 102.5,74.49 103.91,73.91 104.49,72.5 104.49,68.56 103.95,68.24 103.82,68.24 103.82,64.64 104.14,64.64 104.49,64.29 104.49,2.5 103.91,1.09 102.5,0.51 58.25,0.51 57.9,0.65 57.76,1 57.76,5.6 57.32,6.67 56.25,7.11 53.55,7.11 52.84,6.81 52.54,6.1 52.54,0.51 28.31,0.51 28.31,6.1 28.01,6.81 27.3,7.11 24.6,7.11 23.53,6.67 23.09,5.6 23.09,1 22.95,0.65 22.6,0.51 2.5,0.51 1.09,1.09 0.51,2.5 0.51,72.5 1.09,73.91 2.5,74.49 63.15,74.49 63.5,74.35 63.64,74 63.64,69.4 64.08,68.33 65.15,67.89 67.85,67.89 68.56,68.19 68.86,68.9 68.86,74.49 93.09,74.49 93.09,68.9 93.39,68.19 94.1,67.89 96.8,67.89 97.87,68.33 98.31,69.4 ; 46 cut-outs
GND on L05_DGND: 98.31,74 98.45,74.35 98.8,74.49 102.5,74.49 103.91,73.91 104.49,72.5 104.49,2.5 103.91,1.09 102.5,0.51 58.25,0.51 57.9,0.65 57.76,1 57.76,5.6 57.32,6.67 56.25,7.11 53.55,7.11 52.84,6.81 52.54,6.1 52.54,0.51 28.31,0.51 28.31,6.1 28.01,6.81 27.3,7.11 24.6,7.11 23.53,6.67 23.09,5.6 23.09,1 22.95,0.65 22.6,0.51 2.5,0.51 1.09,1.09 0.51,2.5 0.51,72.5 1.09,73.91 2.5,74.49 53.68,74.49 54.52,73.65 54.52,68.82 54.02,68.31 42.84,68.31 41.63,67.1 41.63,62.94 43.24,61.33 73.95,61.33 75.99,63.36 75.99,74.28 76.2,74.49 93.09,74.49 93.09,68.9 93.39,68.19 94.1,67.89 96.8,67.89 97.87,68.33 98.31,69.4 ; 12 cut-outs
VCC1_3.3V on BOTTOM: 28.69,74.41 53.63,74.41 54.52,73.52 54.52,68.82 54.02,68.31 52.21,68.31 51.6,68.92 51.6,71.71 51.05,72.26 51.05,68.83 51.58,68.31 38.34,68.31 38.35,68.33 38.35,69.22 38.48,69.34 38.13,69.69 38.06,69.69 38.06,68.8 37.58,68.31 28.01,68.31 27.65,68.67 27.65,73.37 ; 2 cut-outs
VCC1_3.3V on LO4_SIG2: 52.36,70.73 53.99,70.73 54.86,69.85 55.12,70.1 55.12,70.38 55.16,70.34 55.16,68.31 58.59,64.88 58.59,56.63 58.21,56.25 56.66,56.25 56.31,56.59 56.31,59.03 51.86,63.49 51.86,70.22
VCC1_5V on TOP: 68.24,37.83 68.02,38.05 68.02,40.94 68.36,41.27 76.1,41.27 78.53,38.85 78.53,36.82 78.15,36.44 76.24,36.44 75.99,36.69 75.99,38.21 75.1,39.1 73.95,39.1 73.7,38.85 73.7,37.78 73.65,37.73 71.9,37.73 71.8,37.83 71.8,39.48 71.03,40.25 69.28,40.25 69.06,40.03 69.06,39.09 69.28,38.87 69.99,38.87 70.14,38.72 70.14,37.96 70.02,37.83
VCC1_5V on L03_SIG1: 78.65,39.61 76.24,39.61 75.86,39.23 75.86,38.34 78.02,36.18 85.64,36.18 89.32,39.86 89.32,50.02 94.27,54.98 98.08,54.98 98.59,55.49 98.59,57.52 97.83,58.28 94.27,58.28 86.91,50.91 86.91,48.63 86.02,47.74 79.67,47.74 79.16,47.23 79.16,45.83 79.67,45.33 84.6,45.33 85.72,44.2 85.72,39.5 84.44,38.21 80.05,38.21
VCC1_15V on TOP: 33.7,40.88 29.63,40.88 29.38,40.63 29.38,38.09 30.01,37.45 33.95,37.45 34.29,37.79 34.29,40.29
VCC1_15V on BOTTOM: 55.78,57.66 52.58,57.66 52.24,57.32 52.24,54.98 48.43,51.17 37.38,51.17 35.22,49.01 35.22,43.98 31.37,40.13 31.37,37.97 31.62,37.72 33.84,37.72 37.89,41.77 37.89,46.98 39.03,48.12 50.97,48.12 56.05,53.2 56.05,57.39
VCC1_15V on LO4_SIG2: 45.63,70.73 47.79,70.73 48.3,70.22 48.3,69.07 48.81,68.57 48.81,64.09 55.03,57.87 55.03,56.63 54.78,56.37 52.87,56.37 49.06,60.18 44.49,60.18 41.82,62.85 41.82,67.1 44.83,70.1 44.83,69.92 44.96,70.05 44.96,69.85 45.21,69.85 45.21,70.3
VCC2_3.3V on BOTTOM: 81.6,12.51 81.6,11.19 81.07,10.65 77.61,10.65 73.42,6.46 73.42,4.38 72.96,3.92 67.45,3.92 67.18,4.19 67.18,6.35 68.46,7.63 70.73,7.63 75.81,12.71 81.4,12.71
VCC2_3.3V on L03_SIG1: 84.62,12.05 79.03,12.05 78.53,11.54 78.53,9.61 79.67,8.47 84.01,8.47 85.98,6.5 85.98,4.34 86.45,3.87 95.8,3.87 96.36,4.43 96.36,7.53 95.67,8.22 88.46,8.22
VCC2_5V on TOP: 53.89,37.83 53.38,38.34 53.38,40.68 53.83,41.13 64.28,41.13 64.68,40.73 64.68,36.56 64.3,36.18 61.89,36.18 61.38,36.69 61.38,38.85 61.13,39.1 59.35,39.1 59.22,38.98 59.22,37.91 59.05,37.73 57.17,37.73 57.06,37.83 57.06,39.61 56.43,40.25 55.06,40.25 54.73,39.91 54.73,38.87 55.39,38.87 55.54,38.72 55.54,37.96 55.41,37.83
VCC2_5V on LO4_SIG2: 63.89,39.23 62.65,39.23 61.89,38.47 61.89,34 63.26,32.63 69,32.63 80.84,44.46 80.84,47.2 78.78,49.26 78.78,70.19 78.46,70.51 75.87,70.51 75.54,70.18 75.54,42.72 67.36,34.54 65.41,34.54 64.64,35.31 64.64,38.48
VCC2_15V on TOP: 34.2,37.2 29.63,37.2 29.38,36.94 29.38,34.4 29.63,34.15 32.81,34.15 33.19,33.77 33.19,29.45 33.57,29.07 35.35,29.07 35.73,29.45 35.73,35.04 34.33,36.44 34.33,37.07
VCC2_15V on L03_SIG1: 34.2,36.18 21.63,36.18 15.62,30.17 15.62,28.07 16,27.69 16.82,27.69 22.77,33.64 34.2,33.64 34.58,34.02 34.58,35.8
VCC2_15V on LO4_SIG2: 76.11,7.1 76.11,4.41 75.66,3.95 72.91,3.95 72.43,4.43 72.43,5.96 71.67,6.72 59.07,6.72 56.9,8.89 56.9,11.68 55.89,12.69 21.3,12.69 18.77,15.21 17.55,15.21 15.53,17.23 15.53,29.45 17.15,31.06 18.26,31.06 21.84,27.48 21.84,19.05 25.29,15.61 56.78,15.61 63.51,8.88 74.34,8.88
VCC3_5V on TOP: 37.76,37.83 37.56,38.04 37.56,40.96 37.73,41.13 48.27,41.13 48.81,40.6 48.81,36.56 48.3,36.05 46.14,36.05 45.51,36.69 45.51,38.85 45.25,39.1 43.47,39.1 43.35,38.98 43.35,37.91 43.17,37.73 41.29,37.73 41.19,37.83 41.19,39.61 40.55,40.25 39.23,40.25 38.83,39.84 38.83,38.75 39.31,38.26 39.31,37.83
VCC3_5V on BOTTOM: 37.22,30.47 26.2,30.47 25.69,29.96 25.69,28.18 26.33,27.55 29.63,27.55 31.04,28.96 37.21,28.96 37.47,29.21 37.47,30.23
VCC3_5V on LO4_SIG2: 48.79,38.73 37.9,38.73 35.98,36.82 35.98,29.42 36.45,28.96 37.85,28.96 38.35,29.46 38.35,30.1 38.99,30.73 48.43,30.73 49.44,31.75 49.44,38.09
PWR_IN_5V on BOTTOM: 10.8,18.89 6.51,18.89 5.36,17.74 5.36,10.92 6.11,10.18 8.72,10.18 11.5,12.96 11.5,18.18
PWR_IN_5V on BOTTOM: 74.84,36.44 71.92,36.44 71.29,35.8 71.29,28.99 71.78,28.5 73.58,28.5 74.08,29 74.08,33.39 75.35,34.66 75.35,35.93
PWR_IN_5V on L03_SIG1: 20.71,41.77 44.24,41.77 46.27,39.74 72.81,39.74 75.86,36.69 75.86,35.29 75.35,34.78 36.97,34.78 34.54,37.21 19.36,37.21 15.55,33.4 7.75,33.4 6.6,32.26 6.6,15.87 7.74,14.74 7.75,14.74 7.75,14.35 7.87,14.35 7.87,14.74 8.07,14.74 9.22,13.59 9.14,13.59 8.64,13.08 8.82,13.08 9.82,12.08 9.82,10.91 8.93,10.02 5.76,10.02 2.2,13.58 2.2,36.05 6.93,40.78 17.78,40.78 17.78,40.89 19.05,40.89 19.68,41.53 20.07,41.53 20.07,41.43 21.06,41.43 21.59,40.89 21.72,41.02 21.72,41.15 21.21,41.66 20.83,41.66 ; 3 cut-outs
PWR_IN_24V* on TOP: 23.58,45.71 32.43,45.71 33.19,44.94 33.19,41.52 32.81,41.13 28.43,41.13 27.69,40.39 27.69,34.54 28.33,33.9 32.68,33.9 32.93,33.64 32.93,29.45 32.55,29.07 23.28,29.07 21.5,30.85 21.5,41.15 22.05,41.15 22.05,44.07 21.94,44.07
PWR_IN_24V* on BOTTOM: 9.18,59.17 6.39,59.17 3.98,56.76 3.98,39.61 9.4,34.19 15.57,34.19 17.14,35.76 24.21,35.76 25.19,36.74 25.19,39.74 24.55,40.37 16.31,40.37 14.21,42.47 10.75,42.47 7.41,45.81 7.41,52.44 10.01,55.04 10.01,58.22 10.07,58.28
PWR_OUT_SYS on TOP: 80.56,39.86 80.56,35.42 78.78,33.64 78.78,29.83 78.15,29.2 76.62,29.2 76.11,29.7 76.11,33.39 79.03,36.31 79.03,38.85 76.11,41.77 76.11,45.25 76.68,45.82 78.38,45.82 78.91,45.3 78.91,41.52

Small or netless copper shapes (teardrops, artwork), in the pictures only: 1 on TOP, 2 on L03_SIG1

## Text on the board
BOTTOM: BOTTOM
Ref Des/Assembly Bottom: ASSEMBLY DRAWING BOTTOM
Package Geometry/Pastemask Bottom: PASTE MASK BOTTOM
Ref Des/Silkscreen Bottom: SILKSCREEN BOTTOM
User.Comments: SOLDER MASK TOP | SOLDER MASK BOTTOM
TOP: TOP
Ref Des/Assembly Top: ASSEMBLY DRAWING TOP
Package Geometry/Pastemask Top: PASTE MASK TOP
Ref Des/Silkscreen Top: XMC DRIVE ADAPTER CARD | 600-INT0222-01 REV 03 | 600-INT0222-01 VER1.0 | SILKSCREEN TOP
L02_AGND: L02_AGND
L03_SIG1: L03_SIG1
LO4_SIG2: L04_SIG2
L05_DGND: LO5_DGND
DIMENSION: x4
User.18: 1. SPECIFICATIONS/TOLERANCES: | 2 | 3. DRILLING: | 4. SOLDER MASK: | 5. MARKING: | 6. ELECTRICAL TEST: | 7 | 8. IMPEDANCE: | 9. IF PANELIZATION SPECIFICATIONS ARE PROVIDED, THE PCBS SHALL BE DELIVERED IN | A. FABRICATE PER IPC-6012, CLASS 2, USING PROVIDED DATA FILES | B. ALL SPECIFICATIONS USED SHALL BE PER THEIR LATEST REVISIONS. | C. THE DIMENSIONS OF CIRCUIT FEATURES IN THE PROVIDED DATA MAY BE ADJUSTED | D. REMOVE ALL BURRS AND BREAK SHARP EDGES, .381 [.015] MAX RADIUS. | E. PARENTHETICAL INFORMATION IS FOR REFERENCE ONLY. | F. REPAIR OF PCB DEFECTS IS NOT PERMITTED. | DIELECTRIC MATERIAL: | A. DIELECTRIC MATERIAL SHALL BE PER IPC-4101/99, /124, /126 OR /129 | B. MINIMUM DIELECTRIC THICKNESS SHALL BE .051 [.002] FOR REFERENCED STACK-UP | C. SEE LAYER STACK-UP FOR REQUIRED COPPER WEIGHTS AND THE FINISHED PCB | D. FINISHED PCB THICKNESS SHALL BE MEASURED OVER LANDS AND/OR | A. VIA DIAMETERS (TOL. = +.051/- DRILL DIAMETER [+.0020/- DRILL DIAMETER]) | B. LAYER-TO-LAYER MISREGISTRATION SHALL BE .127 [.005] MAXIMUM. | A. APPLY LPI SOLDER MASK USING PROVIDED DATA. | B. SOLDER MASK SHALL BE PER IPC-SM-840, CLASS T, COLOR RED | C. THE DIMENSIONS OF SOLDER MASK-DEFINED PADS ON PLANES AND/OR WIDE | A. MARK PCB PER PROVIDED DATA USING SILKSCREEN OR AUTOMATED INJET | B. SUPPLIER ID AND TRACEABILITY INFORMATION SHALL BE APPLIED USING | C. INK SHALL NOT BE APPLIED TO ANY SOLDERABLE SURFACE. | A. DESIGN VERIFICATION SHALL BE DONE PRIOR TO PCB FABRICATION USING | B. ALL PCBS SHALL BE 100% ELECTRICALLY TESTED FOR OPENS AND SHORTS | C. APPLY TEST STAMP IN NON-LEGEND AREA ON REAR SIDE OF PCB; OK TO APPLY | FINAL FINISH: | A. FINAL FINISH SHALL BE ELECTROLESS NICKEL/IMMERSION GOLD (ENIG) PER IPC-4552. | A. NOT A IMPEDANCE CONTROLLED BOARD. | PANEL FORM. HOWEVER, THESE SPECIFICATIONS MAY BE CHANGED AS REQUIRED BY THE | CONTRACT MANUFACTURER TO SUPPORT VOLUME ASSEMBLY REQUIREMENTS. | 600-INT0222-01_03.TGZ OR 600-INT0222-01_03.ZIP. | ONLY TO COMPENSATE FOR PROCESS TOLERANCES; ADDING, REMOVING OR RELOCATING | CIRCUIT FEATURES, INCLUDING NON-FUNCTIONAL PADS, IS NOT ALLOWED, AND THE | DESIGN OF ALL PLANE STRUCTURES MUST BE MAINTAINED TO ENSURE PROPER | ELECTRICAL PERFORMANCE. | (RoHS COMPLIANT EPOXY-GLASS). | DIMENSIONS OF.076 [.003] OR GREATER; IPC-6012 REQUIREMENTS SHALL OTHERWISE | APPLY. SINGLE-PLY CONSTRUCTION IS ALLOWED. | THICKNESS. IF SPECIFIED, 1/3 OZ. STARTING FOIL MAY BE ACHIEVED BY 1/2 OZ. | FOIL REDUCTION. | CONDUCTORS NOT COVERED BY SOLDER MASK. | SHALL BE VERIFIED BEFORE PLATING; ALL OTHER HOLE DIAMETERS SHALL BE | VERIFIED AT FINAL INSPECTION. | CONDUCTORS SHALL NOT BE MODIFIED. | PROCESSING WITH PERMANENT, NON-CONDUCTIVE INK, COLOR WHITE. | PERMANENT, NON-CONDUCTIVE INK, COLOR WHITE. | SUPPLIED VALOR ODB++ DATABASE, OR GERBER DATA AND AN IPC-D-356 NETLIST. | USING PROVIDED DATA. | TO PANEL RAILS IF SPACE DOES NOT PERMIT. | NOTES: UNLESS OTHERWISE SPECIFIED
User.19: L05 - PLANE | L06 - BOTTOM | X.X OZ | -- | .----- | --- | ----- | .-----/.----- | (.XXXX) | (UNITS IN MILS)
User.23: 2
User.25: DIMENSIONS IN MM [INCH]
User.40: PROJECT: | DRAWN BY: | LAYER: | DWG NO: | REV: | DATE: | Am Campeon 1-15 | Infineon Technologies AG | 85579 NEUBIBERG - GERMANY | 620-INT0222-01 | ECAD | XMC DRIVE ADAPTER CARD | 03 | 25/03/24
User.45: FIGURE | FINISHED_SIZE | 12.0 | 31.5 | 39.37 | 40.16 | 90.55 | 110.24 | 98.43 | DRILLED_SIZE | - | DRILL CHART: TOP to BOTTOM | ALL UNITS ARE IN MILS | FINISHED_TOL | +3.0/-3.0 | +2.0/-2.0 | DRILLED_TOL | PLATED | NON-PLATED | QTY | 377 | 100 | 56 | 60 | 2 | 4
